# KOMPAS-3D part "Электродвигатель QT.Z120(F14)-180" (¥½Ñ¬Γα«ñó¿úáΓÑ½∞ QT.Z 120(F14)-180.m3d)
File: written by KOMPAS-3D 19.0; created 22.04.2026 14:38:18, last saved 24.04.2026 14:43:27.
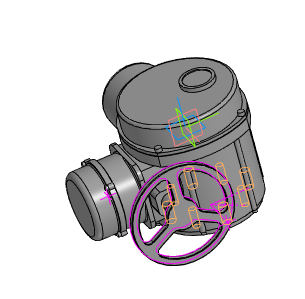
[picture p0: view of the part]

Document properties: Автор: Энергия; Полное имя файла: Z:\3.Личные\kachalov\3d для проектировщиков\1.7 Тип 023F.Z Затвор дисковый поворотный фланцевый с двумя эксцентриками\Привод\Электродвигатель QT.Z 120(F14)-180.m3d

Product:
- Part/product: Электродвигатель QT.Z120(F14)-180
    Масса: 77.5056

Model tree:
1. Эскиз:1
2. Элемент вращения:1
     Угол 1 = 360
3. Эскиз:2  (with: Элемент вращения:1)
4. Элемент выдавливания:1  (with: Элемент вращения:1)
     Расстояние 2 = 70
5. Эскиз:3  (with: Элемент вращения:1)
6. Элемент выдавливания:2
     Расстояние 1 = 147
7. Эскиз:4  (with: Элемент выдавливания:2)
8. Элемент выдавливания:3
     Расстояние 1 = 10
9. Эскиз:5  (with: Элемент выдавливания:2, Элемент выдавливания:3)
10. Элемент выдавливания:4  (with: Элемент вращения:1)
     Расстояние 1 = -147
11. Массив по концентрической сетке:1  (with: Элемент выдавливания:4, Эскиз:5, Элемент выдавливания:2)  (6 pattern instances)
     Шаг 2 = 360
12. Эскиз:6  (with: Элемент выдавливания:1)
13. Элемент выдавливания:5
     Расстояние 1 = 120
14. Эскиз:7  (with: Элемент выдавливания:5)
15. Элемент выдавливания:6
     Расстояние 1 = 10
16. Эскиз:9  (with: Элемент выдавливания:6)
17. Элемент вращения:3
     Угол 1 = 360
18. Эскиз:10  (with: Элемент выдавливания:1)
19. Элемент выдавливания:8
     Расстояние 1 = 110
20. Эскиз:11  (with: Элемент выдавливания:8)
21. Элемент выдавливания:9
     Расстояние 1 = 8
22. Эскиз:12  (with: Элемент выдавливания:9)
23. Элемент выдавливания:10
     Расстояние 1 = 40
24. Эскиз:19  (with: Элемент выдавливания:10)
25. Эскиз:20  (with: Элемент выдавливания:10)
26. Элемент выдавливания:14
     Расстояние 1 = 10
27. Эскиз:21  (with: Элемент выдавливания:14)
28. Элемент выдавливания:15
     Расстояние 1 = 40
29. Скругление:3  (with: Элемент выдавливания:15)
     Радиус = 10
30. Эскиз:22  (with: Элемент вращения:1)
31. Скругление:4  (with: Элемент выдавливания:10, Элемент выдавливания:14, Элемент выдавливания:15)
     Радиус = 2
32. Эскиз:23  (with: Элемент вращения:1)
33. Элемент выдавливания:16
     Расстояние 1 = 8
34. Эскиз:24  (with: Элемент выдавливания:16)
35. Элемент выдавливания:17
     Расстояние 2 = 2
36. Эскиз:25
37. Элемент выдавливания:19
     Расстояние 1 = 97
38. Эскиз:26  (with: Элемент выдавливания:19)
39. Элемент выдавливания:20
     Расстояние 1 = 35
40. Эскиз:27  (with: Элемент выдавливания:20)
41. Элемент выдавливания:21
     Расстояние 1 = 10
42. Эскиз:28  (with: Элемент выдавливания:21)
43. Элемент выдавливания:22
     Расстояние 1 = 10
44. Эскиз:29  (with: Элемент выдавливания:3)
45. Эскиз:30  (with: Элемент выдавливания:3)
46. Элемент выдавливания:23
     Расстояние 2 = 90
47. Эскиз:31  (with: Элемент выдавливания:3)
48. Элемент выдавливания:24
     Расстояние 2 = 2
49. Эскиз:32  (with: Элемент выдавливания:6)
50. Элемент выдавливания:25
     Расстояние 1 = 7
51. Эскиз:33  (with: Элемент вращения:1)
52. Элемент выдавливания:26
     Расстояние 1 = 7
53. Эскиз:34  (with: Элемент выдавливания:14)
54. Элемент выдавливания:27
     Расстояние 1 = 5
55. Скругление:6  (with: Элемент выдавливания:22)
     Радиус = 1
56. Эскиз:35  (with: Элемент выдавливания:2, Элемент выдавливания:4)
57. Элемент выдавливания:28
     Расстояние 1 = 5
58. Скругление:7  (with: Элемент вращения:1)
     Радиус = 5
59. Эскиз:36  (with: Элемент вращения:1)
60. Эскиз:37  (with: Элемент вращения:1)
61. Отверстие:3  (with: Элемент выдавливания:3)  (labels: M16)
     Глубина выреза = 40; Диаметр отверстия = 13.8349; Угол конуса дна = 118; Расстояние 1 = 65; Расстояние 2 = -8; Диаметр зенковки = 18; Глубина зенковки = 2.08253; Угол зенковки = 90
62. M16  (labels: M16; cil0_24705-2004 coarse)
     Длина резьбы = 35; Шаг резьбы = 2; Номинальный диаметр резьбы = 16
63. Отверстие:4  (with: Элемент выдавливания:3)  (labels: M12)
     Глубина выреза = 40; Диаметр отверстия = 10.1056; Угол конуса дна = 118; Расстояние 1 = 39.1942; Расстояние 2 = -52.1942; Диаметр зенковки = 14; Глубина зенковки = 1.94722; Угол зенковки = 90
64. M12  (labels: M12; cil0_24705-2004 coarse)
     Длина резьбы = 35; Шаг резьбы = 1.75; Номинальный диаметр резьбы = 12
65. Массив по концентрической сетке:4  (with: Отверстие:3, Эскиз:29, M12)  (labels: M16; cil0_24705-2004 coarse)  (3 pattern instances)
     Длина резьбы = 35; Шаг резьбы = 2; Номинальный диаметр резьбы = 16
66. Отверстие:3  (with: Эскиз:29)  (labels: M16)
67. Массив по концентрической сетке:5  (with: Отверстие:4, Эскиз:29)  (labels: M12)  (2 pattern instances)
68. M10  (with: Отверстие:4, Эскиз:29)  (labels: M12; cil0_24705-2004 coarse)  (1 pattern instances)
     Длина резьбы = 35; Шаг резьбы = 1.75; Номинальный диаметр резьбы = 12
69. Отверстие:4  (with: Эскиз:29)  (labels: M12)
70. Эскиз:38  (with: Элемент вращения:1)

Expressions: 360/4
